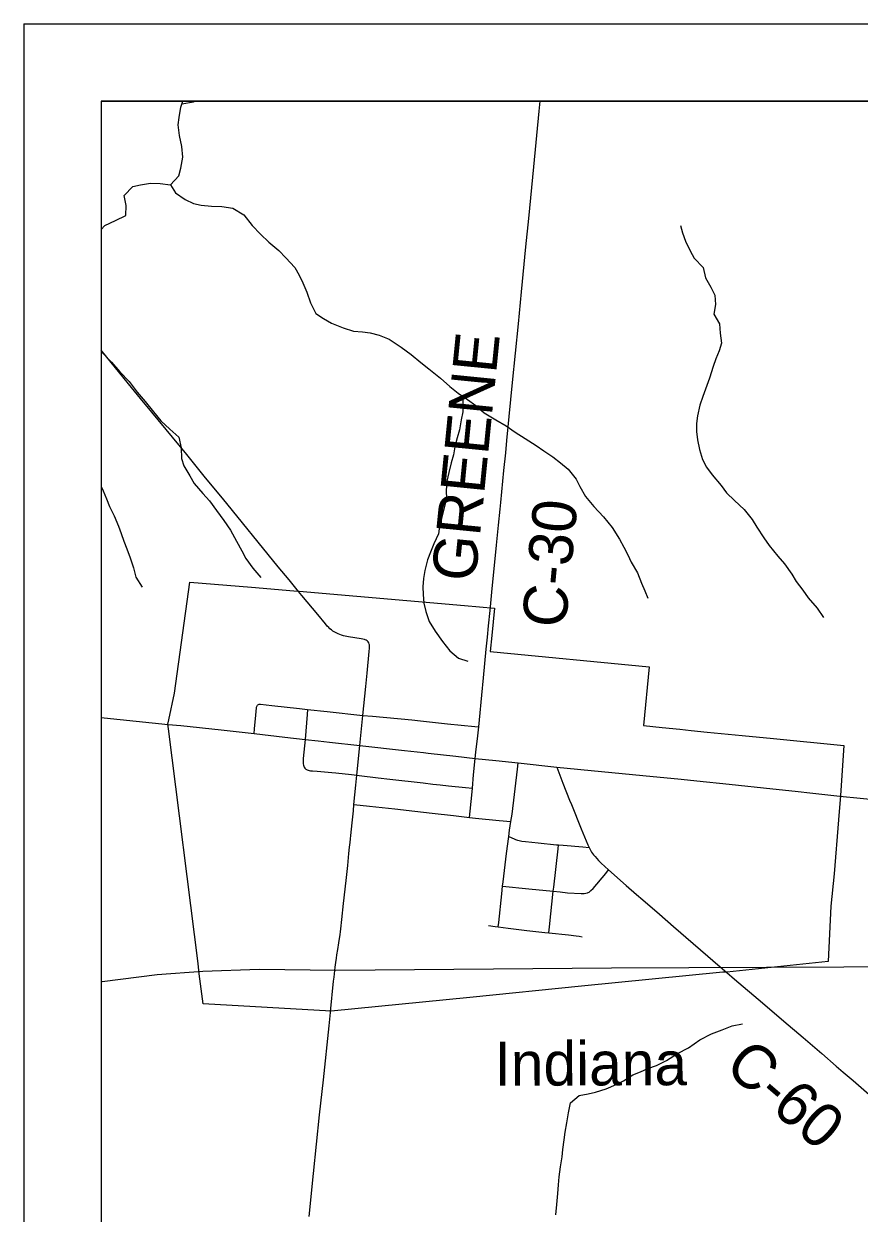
# Model space of a CAD drawing. Extents: x 0 to 48.6, y 0 to 22.
# Drawn here: x 2 to 3.078, y 19.466 to 21 of the extents above; entities that cross this region are included whole.
import ezdxf

# ---------------------------------------------------------------- set-up
doc = ezdxf.new("R2010")
doc.units = 0
for name, color, linetype in [('GM_X_City_Street', 7, 'Continuous'), ('GM_X_Corporation', 7, 'Continuous'), ('GM_X_County_Road', 7, 'Continuous'), ('GM_X_County_Road_Text', 7, 'Continuous'), ('GM_X_Minor_River', 7, 'Continuous'), ('GM_X_Rail_Line', 7, 'Continuous'), ('GM_X_Rail_Line_Text', 7, 'Continuous'), ('GM_X_State_Route', 7, 'Continuous'), ('GM_X_Township_Road', 7, 'Continuous'), ('SH_Data', 7, 'Continuous')]:
    doc.layers.add(name, color=color, linetype=linetype)

msp = doc.modelspace()

# ---------------------------------------------------------------- linework, layer by layer
at = {"layer": 'GM_X_City_Street'}
for points in [[(2.2973, 20.0843), (2.2978, 20.0903), (2.2992, 20.1083), (2.3002, 20.1175), (2.3004, 20.1186), (2.3006, 20.1194), (2.301, 20.1203), (2.3014, 20.121), (2.302, 20.1216), (2.3028, 20.1221), (2.3037, 20.1224), (2.3045, 20.1225), (2.3052, 20.1224), (2.3201, 20.1208), (2.3557, 20.1168), (2.3662, 20.1156), (2.3913, 20.1128), (2.4373, 20.1078), (2.4499, 20.1067), (2.5006, 20.1019), (2.5117, 20.1008), (2.5468, 20.0971), (2.5819, 20.0935), (2.587, 20.0929)], [(2.3662, 20.1156), (2.3657, 20.1091), (2.3629, 20.0769), (2.3606, 20.0523), (2.3604, 20.0497), (2.3604, 20.0475), (2.3605, 20.0454), (2.3608, 20.0436), (2.3616, 20.0412), (2.3626, 20.0397), (2.364, 20.0385), (2.3656, 20.0376), (2.368, 20.0369), (2.3699, 20.0365), (2.3723, 20.0362), (2.3784, 20.0357), (2.3976, 20.0342), (2.4025, 20.0336), (2.4229, 20.0316), (2.4296, 20.0306), (2.4328, 20.0302), (2.4574, 20.0271), (2.4722, 20.0254), (2.5154, 20.0207), (2.5277, 20.0192), (2.537, 20.0181), (2.5481, 20.017), (2.5701, 20.0148), (2.5789, 20.014)], [(2.5752, 19.9763), (2.576, 19.9844), (2.5785, 20.0094), (2.5789, 20.014), (2.5804, 20.031), (2.5825, 20.0523)], [(2.612, 19.8352), (2.6127, 19.8408), (2.6168, 19.8777), (2.6178, 19.8875), (2.6183, 19.8931), (2.6226, 19.9295), (2.6256, 19.9515), (2.6266, 19.9596), (2.6284, 19.9708), (2.6299, 19.9806), (2.6368, 20.0385), (2.6378, 20.0465)], [(2.426, 19.9928), (2.4461, 19.9906), (2.4787, 19.9871), (2.5046, 19.9842), (2.5268, 19.9817), (2.5546, 19.9788), (2.5752, 19.9763), (2.5829, 19.9754), (2.6132, 19.9724), (2.6284, 19.9708)], [(2.6256, 19.9515), (2.6329, 19.9484), (2.6346, 19.9476), (2.637, 19.9469), (2.6391, 19.9463), (2.6425, 19.9456), (2.6474, 19.9451), (2.6636, 19.9435), (2.6871, 19.941), (2.6899, 19.9408), (2.6958, 19.9403), (2.7212, 19.9381), (2.7293, 19.9374)], [(2.6775, 19.8274), (2.6783, 19.835), (2.6832, 19.8811), (2.6837, 19.8863), (2.6894, 19.9358), (2.6899, 19.9408)], [(2.6178, 19.8875), (2.6516, 19.8841), (2.6832, 19.8811), (2.6919, 19.8802), (2.7017, 19.8791), (2.7191, 19.878), (2.7208, 19.8779), (2.7229, 19.878), (2.7253, 19.8784), (2.7271, 19.8789), (2.7283, 19.8795), (2.7293, 19.88), (2.7304, 19.8808), (2.7318, 19.8819), (2.7345, 19.8845), (2.7509, 19.904), (2.7546, 19.9085)], [(2.5997, 19.837), (2.6083, 19.8357), (2.612, 19.8352), (2.6249, 19.8333), (2.6352, 19.832), (2.6489, 19.8303), (2.6724, 19.8279), (2.6775, 19.8274), (2.7026, 19.8247), (2.7125, 19.8236), (2.7164, 19.8232), (2.7205, 19.8224)]]:
    msp.add_lwpolyline(points, dxfattribs=at)
at = {"layer": 'GM_X_Corporation'}
for points in [[(8.9, 20.9), (2.1, 20.9), (2.1, 14.1)], [(5.5264, 17.0064), (5.8387, 17.2541), (6.5365, 17.7727), (6.4996, 17.9212), (6.3396, 18.6531), (6.2759, 18.9159), (6.0412, 19.8859), (5.8236, 20.7829), (5.795, 20.9), (2.1, 20.9), (2.1, 14.1)]]:
    msp.add_lwpolyline(points, dxfattribs=at)
msp.add_lwpolyline([(2.2143, 20.2798), (2.2936, 20.2731), (2.3483, 20.2685), (2.3551, 20.2679), (2.5684, 20.2498), (2.6073, 20.246), (2.6039, 20.2108), (2.6018, 20.1901), (2.8069, 20.1703), (2.7997, 20.0946), (2.8235, 20.0922), (2.8465, 20.0899), (2.8612, 20.0885), (2.8819, 20.0864), (2.9269, 20.0819), (2.9674, 20.0779), (3.058, 20.0688), (3.0537, 20.0045), (3.0511, 19.9733), (3.0457, 19.9035), (3.0411, 19.8618), (3.0379, 19.7904), (2.9072, 19.7768), (2.9019, 19.7765), (2.7196, 19.7584), (2.5753, 19.7441), (2.3965, 19.7261), (2.2313, 19.7356), (2.2264, 19.7744), (2.2248, 19.7876), (2.1869, 20.0903), (2.186, 20.0966), (2.1872, 20.1023), (2.1945, 20.1367)], close=True, dxfattribs=at)
at = {"layer": 'GM_X_County_Road'}
for p, q in [((2.4296, 20.0306), (2.4334, 20.0691)), ((2.9069, 19.7762), (2.9169, 19.7677))]:
    msp.add_line(p, q, dxfattribs=at)
for points in [[(2.6016, 20.2433), (2.6044, 20.2717), (2.6065, 20.2928), (2.6101, 20.3274), (2.6125, 20.3533), (2.6146, 20.3737), (2.6156, 20.3826), (2.6195, 20.4236), (2.6219, 20.4465), (2.6233, 20.4626), (2.6263, 20.4935), (2.6305, 20.5374), (2.6381, 20.6128), (2.642, 20.6542), (2.6476, 20.7123), (2.6514, 20.7487), (2.6581, 20.8155), (2.6651, 20.8872), (2.6664, 20.9)], [(2.5967, 20.1934), (2.5981, 20.2086), (2.5995, 20.2235), (2.6016, 20.2433)], [(2.587, 20.0929), (2.5879, 20.1023), (2.591, 20.1339), (2.5931, 20.1562), (2.5967, 20.1934)], [(2.5825, 20.0523), (2.5834, 20.0603), (2.5858, 20.0813), (2.587, 20.0929)], [(2.6879, 20.0412), (2.6955, 20.0206), (2.7042, 19.9986), (2.7065, 19.9929), (2.719, 19.9617), (2.7276, 19.941), (2.7293, 19.9374)], [(2.426, 19.9928), (2.4283, 20.018), (2.4296, 20.0306)], [(2.3958, 19.7246), (2.3959, 19.7256), (2.3998, 19.7652), (2.4004, 19.7703), (2.4014, 19.7787), (2.4019, 19.783), (2.4027, 19.789), (2.4034, 19.7946), (2.4039, 19.7991), (2.405, 19.806), (2.4063, 19.8144), (2.408, 19.8253), (2.4085, 19.8285), (2.409, 19.8326), (2.4105, 19.8445), (2.4126, 19.8654), (2.4158, 19.895), (2.418, 19.9144), (2.4194, 19.9296), (2.4203, 19.9377), (2.421, 19.9438), (2.4215, 19.9488), (2.4219, 19.9528), (2.4236, 19.9692), (2.4252, 19.9847), (2.426, 19.9928)], [(2.7293, 19.9374), (2.7306, 19.9347), (2.7326, 19.9316), (2.7339, 19.9297), (2.7352, 19.928), (2.737, 19.9258), (2.7393, 19.9232), (2.7416, 19.9206), (2.7449, 19.9173), (2.7495, 19.9131), (2.7546, 19.9085)], [(2.7546, 19.9085), (2.7774, 19.8884), (2.7905, 19.877), (2.7985, 19.87), (2.8201, 19.8513), (2.8384, 19.8354), (2.8986, 19.7833), (2.9069, 19.7762)], [(2.9169, 19.7677), (2.953, 19.737), (2.9804, 19.7136), (3.0055, 19.6923), (3.0297, 19.6718), (3.0483, 19.6554), (3.0573, 19.6477), (3.07, 19.6367), (3.0905, 19.6187)], [(2.368, 19.4615), (2.374, 19.5171), (2.3817, 19.5925), (2.3867, 19.6376), (2.3939, 19.7074), (2.3958, 19.7246)]]:
    msp.add_lwpolyline(points, dxfattribs=at)
at = {"layer": 'GM_X_Minor_River'}
for points in [[(2.1, 20.7347), (2.1044, 20.74), (2.1182, 20.7463), (2.1316, 20.7526), (2.1321, 20.7655), (2.1293, 20.7784), (2.1408, 20.7901), (2.1507, 20.7922), (2.1633, 20.7943), (2.1758, 20.7938), (2.1895, 20.7921), (2.1999, 20.8037), (2.2027, 20.8139), (2.2051, 20.8279), (2.2038, 20.8416), (2.2009, 20.8557), (2.1992, 20.8698), (2.2005, 20.8793), (2.2026, 20.8925), (2.205, 20.9)], [(2.204, 20.8968), (2.219, 20.8995), (2.2209, 20.9)], [(2.1895, 20.7921), (2.1958, 20.7821), (2.2082, 20.7732), (2.2188, 20.7682), (2.229, 20.7661), (2.2423, 20.7648), (2.2556, 20.7643), (2.2696, 20.7622), (2.2839, 20.7537), (2.2947, 20.7399), (2.3052, 20.7287), (2.3161, 20.7183), (2.3292, 20.7075), (2.3382, 20.6979), (2.3495, 20.6856), (2.3554, 20.6757), (2.3602, 20.6657), (2.365, 20.6539), (2.3701, 20.6402), (2.3768, 20.6264), (2.3869, 20.6198), (2.3971, 20.6136), (2.4122, 20.6077), (2.4255, 20.6034), (2.4368, 20.6025), (2.4471, 20.6012), (2.4584, 20.5984), (2.4713, 20.5933), (2.4867, 20.5829), (2.4999, 20.5732), (2.5123, 20.5632), (2.5228, 20.5551), (2.5375, 20.5427), (2.5495, 20.5323), (2.5604, 20.5235), (2.5724, 20.5153), (2.5833, 20.5076), (2.5938, 20.498), (2.6089, 20.489), (2.6225, 20.4813), (2.6341, 20.4731), (2.6469, 20.465), (2.6609, 20.4561), (2.671, 20.4491), (2.6827, 20.4414), (2.6925, 20.4337), (2.7022, 20.4256), (2.7127, 20.4125), (2.7175, 20.403), (2.7246, 20.39), (2.7354, 20.3773), (2.7481, 20.3639), (2.759, 20.3501), (2.7686, 20.3351), (2.7742, 20.3248), (2.7794, 20.3149), (2.7838, 20.3053), (2.7916, 20.2919), (2.7968, 20.2786), (2.8012, 20.2687), (2.8052, 20.2591)], [(2.8473, 20.7398), (2.8499, 20.7304), (2.8539, 20.7197), (2.8598, 20.7071), (2.865, 20.6975), (2.8766, 20.6856), (2.8795, 20.6723), (2.8866, 20.6601), (2.8914, 20.6501), (2.8923, 20.638), (2.8903, 20.6255), (2.8977, 20.6128), (2.8983, 20.6011), (2.9004, 20.5881), (2.8972, 20.5783), (2.8929, 20.5677), (2.8894, 20.5579), (2.8846, 20.5428), (2.8763, 20.519), (2.8724, 20.508), (2.8692, 20.4944), (2.8679, 20.4842), (2.8681, 20.4739), (2.8691, 20.4633), (2.8716, 20.4507), (2.8756, 20.4381), (2.8808, 20.4282), (2.8883, 20.4182), (2.8999, 20.4044), (2.9066, 20.3948), (2.9171, 20.3852), (2.9294, 20.3733), (2.9399, 20.3606), (2.9458, 20.3507), (2.9548, 20.3369), (2.9619, 20.3269), (2.9727, 20.3131), (2.9813, 20.3035), (2.991, 20.2901), (2.9966, 20.2805), (3.0052, 20.2694), (3.0122, 20.2595), (3.0238, 20.246), (3.0317, 20.2342)], [(2.1, 20.578), (2.1022, 20.5753), (2.1131, 20.5634), (2.1239, 20.5511), (2.1359, 20.5384), (2.1464, 20.525), (2.1568, 20.5127), (2.1673, 20.4993), (2.177, 20.4878), (2.1883, 20.477), (2.1999, 20.4666), (2.2031, 20.4529), (2.2033, 20.4392), (2.2066, 20.4297), (2.2141, 20.4167), (2.22, 20.4071), (2.2312, 20.3941), (2.2395, 20.3845), (2.2488, 20.3722), (2.2581, 20.3592), (2.2667, 20.3466), (2.2745, 20.3328), (2.2815, 20.3202), (2.2867, 20.3102), (2.2956, 20.2976), (2.3057, 20.2857)], [(2.5664, 20.5194), (2.5665, 20.4995), (2.5641, 20.4889), (2.562, 20.476), (2.5592, 20.4661), (2.556, 20.4544), (2.5544, 20.4438), (2.5516, 20.4336), (2.5484, 20.4211), (2.5459, 20.4098), (2.545, 20.3976), (2.5453, 20.3877), (2.542, 20.3737), (2.5392, 20.3635), (2.5364, 20.3518), (2.5351, 20.3419), (2.5289, 20.3291), (2.5246, 20.3185), (2.521, 20.3087), (2.5174, 20.2947), (2.5158, 20.2845), (2.5149, 20.2735), (2.5151, 20.2636), (2.5161, 20.2526), (2.5186, 20.2419), (2.523, 20.229), (2.5308, 20.2164), (2.5401, 20.2033), (2.5495, 20.1911), (2.5607, 20.1818), (2.5728, 20.1778)], [(2.1, 20.4031), (2.1025, 20.3977), (2.1069, 20.387), (2.1106, 20.3771), (2.1165, 20.3652), (2.1224, 20.3518), (2.1257, 20.3423), (2.129, 20.3324), (2.133, 20.3229), (2.1374, 20.311), (2.1414, 20.2981), (2.1447, 20.2863), (2.1529, 20.2733)], [(2.6864, 19.4635), (2.6877, 19.4767), (2.689, 19.4911), (2.6899, 19.5021), (2.6908, 19.5124), (2.6925, 19.5253), (2.6946, 19.5385), (2.6955, 19.548), (2.6972, 19.5605), (2.6984, 19.5704), (2.7005, 19.5821), (2.7029, 19.595), (2.7054, 19.6082), (2.7165, 19.6176), (2.728, 19.6197), (2.7375, 19.6219), (2.7512, 19.6262), (2.7642, 19.6318), (2.7738, 19.6366), (2.786, 19.644), (2.7956, 19.6481), (2.8051, 19.6525), (2.8162, 19.6561), (2.8292, 19.6628), (2.8434, 19.6717), (2.8575, 19.6788), (2.8721, 19.6892), (2.8874, 19.697), (2.9011, 19.7021), (2.9141, 19.7073), (2.9274, 19.7101)]]:
    msp.add_lwpolyline(points, dxfattribs=at)
at = {"layer": 'GM_X_Rail_Line'}
msp.add_lwpolyline([(2.1, 19.7643), (2.1011, 19.7645), (2.172, 19.7738), (2.2311, 19.7779), (2.3038, 19.7803), (2.4027, 19.7791), (2.7583, 19.782), (3.4579, 19.785), (4.2295, 19.785), (4.6206, 19.7852), (5.0462, 19.7937), (5.6922, 19.8043), (6.0216, 19.8102), (6.7352, 19.82), (7.2096, 19.8291), (8.1004, 19.8459), (8.9, 19.8619)], dxfattribs=at)
at = {"layer": 'GM_X_State_Route'}
for points in [[(2.1, 20.105), (2.1035, 20.1046), (2.1864, 20.0961)], [(2.1864, 20.0961), (2.2027, 20.0947), (2.2546, 20.0891), (2.2973, 20.0843), (2.3367, 20.0799), (2.3629, 20.0769), (2.3798, 20.0749)], [(2.3798, 20.0749), (2.3946, 20.0732), (2.4334, 20.0691)], [(2.4334, 20.0691), (2.491, 20.0626), (2.5156, 20.0599)], [(2.5156, 20.0599), (2.5216, 20.0593), (2.5574, 20.0553), (2.5825, 20.0523), (2.6092, 20.0496), (2.6378, 20.0465), (2.6879, 20.0412), (2.7454, 20.0355), (2.7988, 20.0305), (2.8481, 20.0255)], [(2.8481, 20.0255), (2.8767, 20.0226), (2.9021, 20.0199), (2.9744, 20.0124), (2.9954, 20.01), (3.0182, 20.0075), (3.0528, 20.0036)], [(3.0528, 20.0036), (3.1052, 19.9983), (3.1435, 19.9942), (3.1941, 19.9889), (3.2664, 19.9816), (3.3418, 19.9737), (3.3956, 19.9684), (3.4283, 19.9651), (3.466, 19.9613), (3.4736, 19.9606), (3.5082, 19.957), (3.5329, 19.9544), (3.6071, 19.9469), (3.6349, 19.9443), (3.7103, 19.9366), (3.8081, 19.9274), (3.9286, 19.9157), (4.0331, 19.9053), (4.0591, 19.9026), (4.0733, 19.9013), (4.0875, 19.8999), (4.1135, 19.897), (4.1327, 19.8955), (4.1538, 19.8938)]]:
    msp.add_lwpolyline(points, dxfattribs=at)
at = {"layer": 'GM_X_Township_Road'}
msp.add_line((2.4334, 20.0691), (2.4373, 20.1078), dxfattribs=at)
for points in [[(2.3545, 20.2678), (2.3423, 20.2827), (2.3284, 20.2994), (2.2562, 20.3879), (2.2346, 20.4144), (2.2102, 20.4442), (2.1653, 20.499), (2.1507, 20.5167), (2.1353, 20.5354), (2.1, 20.579)], [(2.4373, 20.1078), (2.4411, 20.1452), (2.4429, 20.1625), (2.4458, 20.1903), (2.4462, 20.1945), (2.4461, 20.1963), (2.4461, 20.1975), (2.4459, 20.1988), (2.4457, 20.1998), (2.4451, 20.2014), (2.4442, 20.2028), (2.443, 20.2039), (2.4416, 20.2048), (2.4406, 20.2053), (2.4395, 20.2056), (2.4376, 20.2061), (2.4353, 20.2065), (2.4188, 20.2092), (2.4126, 20.2105), (2.4101, 20.2112), (2.4078, 20.212), (2.4058, 20.2129), (2.4037, 20.2137), (2.402, 20.2147), (2.4004, 20.2156), (2.3987, 20.2167), (2.3968, 20.2181), (2.395, 20.2197), (2.3934, 20.2211), (2.3916, 20.2231), (2.3892, 20.2258), (2.3793, 20.2378), (2.3588, 20.2627), (2.3545, 20.2678)]]:
    msp.add_lwpolyline(points, dxfattribs=at)
at = {"layer": 'SH_Data'}
for p, q in [((2, 21), (9, 21)), ((2, 21), (2, 14)), ((2.1, 20.9), (2.1, 14.1)), ((2.1, 20.9), (8.9, 20.9))]:
    msp.add_line(p, q, dxfattribs=at)

# ---------------------------------------------------------------- texts
at = {"layer": 'GM_X_County_Road_Text'}
for s, rotation, p in [('GREENE', 84.324, (2.5826, 20.2791)), ('C-30', 84.5353, (2.699, 20.2194)), ('C-60', 319.3653, (2.9019, 19.6515))]:
    msp.add_text(s, height=0.05682, rotation=rotation, dxfattribs=at).set_placement(p)
at = {"layer": 'GM_X_Rail_Line_Text'}
msp.add_text('Indiana', height=0.05663, rotation=0.1716, dxfattribs=at).set_placement((2.6074, 19.6301))

doc.saveas('drawing.dxf')
